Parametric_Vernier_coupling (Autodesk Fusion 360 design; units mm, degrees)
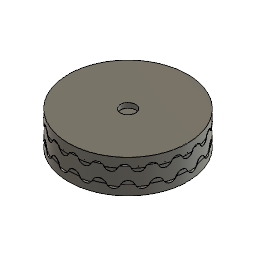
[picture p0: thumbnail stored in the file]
parameter "OD" = 50
parameter "ID" = 25
parameter "Bolt" = 6.3
parameter "Separation" = 6
parameter "Thickness" = 4
parameter "PressureAngle" = 20
parameter "WasherThickness" = 7.5
sketch "Sketch1" plane through (0, 0, 0) normal (1, 0, 0) x axis (0, 0, -1)
  line L1 (0, 7) -> (0, 0)
  line L2 (-25, 7) -> (-3.15, 7)
  line L3 (-25, -7) -> (-3.15, -7)
  line L4 (0, -7) -> (0, 0)
  line L5 (-3.15, -5) -> (-3.15, -7)
  line L6 (-12.5, -5) -> (-3.15, -5)
  line L7 (-12.5, -3) -> (-12.5, -5)
  line L8 (-25, -3) -> (-12.5, -3)
  line L9 (-25, -7) -> (-25, -3)
  line L10 (-25, 3) -> (-25, 7)
  line L11 (-12.5, 3) -> (-25, 3)
  line L12 (-12.5, 5) -> (-12.5, 3)
  line L13 (-3.15, 5) -> (-12.5, 5)
  line L14 (-3.15, 7) -> (-3.15, 5)
  line L15 (-12.5, -3) -> (-12.5, 3)
  line L16 (0, -7) -> (-3.15, -7)
  line L17 (0, 7) -> (-3.15, 7)
  point P1 (0, 0)
  point P2 (0, 0)
  point P8 (0, 0)
  point P3 (0, 7)
  point P9 (0, -7)
  point P6 (-3.15, -7)
  point P10 (-3.15, -7)
  point P4 (-3.15, 7)
  point P18 (-3.15, 5)
  coincident P1 P2
  vertical L1
  horizontal L2
  perpendicular L1 L3
  coincident P1 P8
  parallel L1 L4
  equal L1 L4
  coincident P3 L2
  coincident L3 P9
  perpendicular L3 L5
  perpendicular L5 L6
  perpendicular L6 L7
  perpendicular L2 L10
  perpendicular L10 L11
  perpendicular L11 L12
  collinear L9 L10
  parallel L3 L8
  parallel L2 L13
  collinear L7 L12
  coincident P6 P10
  equal L5 L14
  collinear L5 L14
  dimension "d7" = 6.3 (= "Bolt")
  dimension "d8" = 50 (= "OD")
  dimension "d12" distance L2 L11 = 4 (= "Thickness")
  dimension "d13" distance L3 L8 = 4 (= "Thickness")
  dimension "d14" distance L8 L11 = 6 (= "Separation")
  dimension "d15" = 25 (= "ID")
  dimension "d16" distance P4 P18 = 2 (= "Thickness / 2")
revolve "Revolve1" sketch "Sketch1" AlongAngle 360
sketch "Sketch2" plane through (0, -3, 0) normal (0, 1, 0) x axis (-1, 0, 0)
  line L1 (0, 25) -> (0, 0)
  line L2 (2.1789, 24.9049) -> (0, 0)
  line L3 (-2.1789, 24.9049) -> (2.1789, 24.9049)
  line L4 (0, 0) -> (-2.1789, 24.9049)
  circle C1 centre (0, 0) radius 25
  circle C2 centre (0, 0) radius 12.5
  point P1 (0, 0)
  point P3 (0, 0)
  point P4 (0, 25)
  point P2 (0, 0)
  point P5 (0, 0)
  point P6 (2.1789, 24.9049)
  point P7 (-2.1789, 24.9049)
  coincident P1 P3
  coincident C1 P4
  vertical L1
  coincident P2 P5
  coincident C1 P6
  coincident C1 P7
  perpendicular L1 L3
  dimension "d18" angle L1 L2 = 5 (= "( 90 / N1 ) * 1 deg")
sketch "Sketch3" plane through (0, 3, 0) normal (0, -1, 0) x axis (1, 0, 0)
  line L1 (0, 25) -> (0, 0)
  line L2 (-2.0645, 24.9146) -> (0, 0)
  line L3 (2.0645, 24.9146) -> (-2.0645, 24.9146)
  line L4 (0, 0) -> (2.0645, 24.9146)
  circle C1 centre (0, 0) radius 12.5
  circle C2 centre (0, 0) radius 25
  point P1 (0, 0)
  point P4 (0, 0)
  point P3 (0, 25)
  point P5 (0, 25)
  point P6 (0, 0)
  point P7 (-2.0645, 24.9146)
  point P8 (2.0645, 24.9146)
  coincident P1 P4
  coincident P3 P5
  coincident P1 P6
  coincident C2 P7
  coincident C2 P8
  perpendicular L1 L3
  dimension "d19" angle L1 L4 = 4.737 (= "( 90 / N2 ) * 1 deg")
work_plane "WorkPlane1"
sketch "Sketch4" plane through (0, -0.0405, 24.9097) normal (0, 0.0016, -1) x axis (-1, 0, 0)
  line L1 (-2.1789, -6.9428) -> (-2.1789, -2.9595)
  line L2 (2.1789, 1.0237) -> (2.1789, -2.9595)
  line L3 (2.0645, 6.9557) -> (2.0645, 3.0405)
  line L4 (-2.0645, -0.8748) -> (-2.0645, 3.0405)
  point P2 (-2.1789, -2.9595)
  point P6 (-2.1789, -2.9595)
  point P3 (2.1789, -2.9595)
  point P8 (2.1789, -2.9595)
  point P5 (2.0645, 3.0405)
  point P10 (2.0645, 3.0405)
  point P4 (-2.0645, 3.0405)
  point P12 (-2.0645, 3.0405)
  coincident P2 P6
  vertical L1
  coincident P3 P8
  parallel L1 L2
  coincident P5 P10
  parallel L2 L3
  coincident P4 P12
  parallel L3 L4
  equal L1 L2
  equal L3 L4
work_plane "WorkPlane2"
work_plane "WorkPlane3"
work_axis "WorkAxis1"
sketch "Sketch5" plane through (-0.9642, -2.6491, 0) normal (0.342, 0.9397, 0) x axis (0, 0, 1)
  line L1 (0, 1.0261) -> (24.9036, 3.3448)
  line L2 (24.9062, -1.2927) -> (0, 1.0261)
  line L3 (25, 1.0261) -> (0, 1.0261)
  line L4 (24.9036, 3.3448) -> (25, 1.0261)
  line L5 (25.1816, 1.0261) -> (25, 1.0261)
  line L6 (25.087, -1.3095) -> (25.1816, 1.0261)
  line L7 (25.087, -1.3095) -> (24.9062, -1.2927)
  point P2 (24.9036, 3.3448)
  point P5 (24.9036, 3.3448)
  point P3 (24.9062, -1.2927)
  point P7 (24.9062, -1.2927)
  point P4 (25, 1.0261)
  point P8 (25, 1.0261)
  point P9 (25, 1.0261)
  point P10 (24.9036, 3.3448)
  point P11 (0, 1.0261)
  point P12 (0, 1.0261)
  point P6 (0, 1.0261)
  coincident P2 P5
  coincident P3 P7
  coincident P4 P8
  coincident P4 P9
  coincident P2 P10
  coincident P11 P12
  coincident P6 P11
  parallel L3 L5
  collinear L2 L7
  equal L5 L7
sketch "Sketch6" plane through (0.9642, 2.6491, 0) normal (0.342, 0.9397, 0) x axis (0, 0, 1)
  line L1 (0, -1.0261) -> (25, -1.0261)
  line L2 (24.9134, 1.1709) -> (0, -1.0261)
  line L3 (24.9158, -3.223) -> (25, -1.0261)
  line L4 (0, -1.0261) -> (24.9158, -3.223)
  line L5 (25.2373, -1.0358) -> (25, -1.0261)
  line L6 (25.1953, 1.1958) -> (25.2373, -1.0358)
  line L7 (24.9134, 1.1709) -> (25.1953, 1.1958)
  point P4 (25, -1.0261)
  point P6 (25, -1.0261)
  point P2 (24.9134, 1.1709)
  point P7 (24.9134, 1.1709)
  point P8 (25, -1.0261)
  point P3 (24.9158, -3.223)
  point P9 (24.9158, -3.223)
  point P13 (0, -1.0261)
  point P14 (0, -1.0261)
  point P10 (0, -1.0261)
  coincident P4 P6
  coincident P2 P7
  coincident P4 P8
  coincident P3 P9
  collinear L2 L7
  coincident P13 P14
  coincident P10 P13
revolve "Revolve2" sketch "Sketch6" AlongAngle 360
revolve "Revolve3" sketch "Sketch6" AlongAngle 360
circular_pattern "C-Pattern1" countU 19 (= "N2") TotalAngle 360
revolve "Revolve4" sketch "Sketch5" AlongAngle 360
revolve "Revolve5" sketch "Sketch5" AlongAngle 360
circular_pattern "C-Pattern2" countU 18 (= "N1") TotalAngle 360
revolve "Revolve6" sketch "Sketch1" AlongAngle 360
sketch "Sketch7" plane through (0, 0, 0) normal (1, 0, 0) x axis (0, 0, -1)
  line L1 (0, -2.098) -> (0, 2.098)
  line L2 (-3.15, -1.0891) -> (-3.15, 1.5562)
  line L3 (-12.5, -1.0891) -> (-3.15, -1.0891)
  line L4 (-12.5, -3.75) -> (-12.5, -1.0891)
  line L5 (-24.875, -3.75) -> (-12.5, -3.75)
  line L6 (-24.875, 3.75) -> (-24.875, -3.75)
  line L7 (-12.5, 3.75) -> (-24.875, 3.75)
  line L8 (-12.5, 1.5562) -> (-12.5, 3.75)
  line L9 (-3.15, 1.5562) -> (-12.5, 1.5562)
  line L10 (-24.875, 0) -> (0, 0)
  point P1 (0, 0)
  point P12 (0, 0)
  point P13 (-24.875, 0)
  point P7 (-24.875, -3.75)
  point P8 (-24.875, 3.75)
  vertical L1
  midpoint P1 L1
  vertical L2
  perpendicular L2 L3
  perpendicular L3 L4
  perpendicular L4 L5
  perpendicular L5 L6
  perpendicular L6 L7
  perpendicular L7 L8
  perpendicular L2 L9
  collinear L4 L8
  coincident P1 P12
  coincident L6 P13
  perpendicular L6 L10
  symmetric L5 L7 L10
  dimension "d31" = 6.3 (= "Bolt")
  dimension "d32" = 25 (= "ID")
  dimension "d33" = 49.75 (= "OD * 0.995")
  dimension "d36" distance P7 P8 = 7.5 (= "WasherThickness")
revolve "Revolve7" sketch "Sketch7" AlongAngle 360
combine "Combine1"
